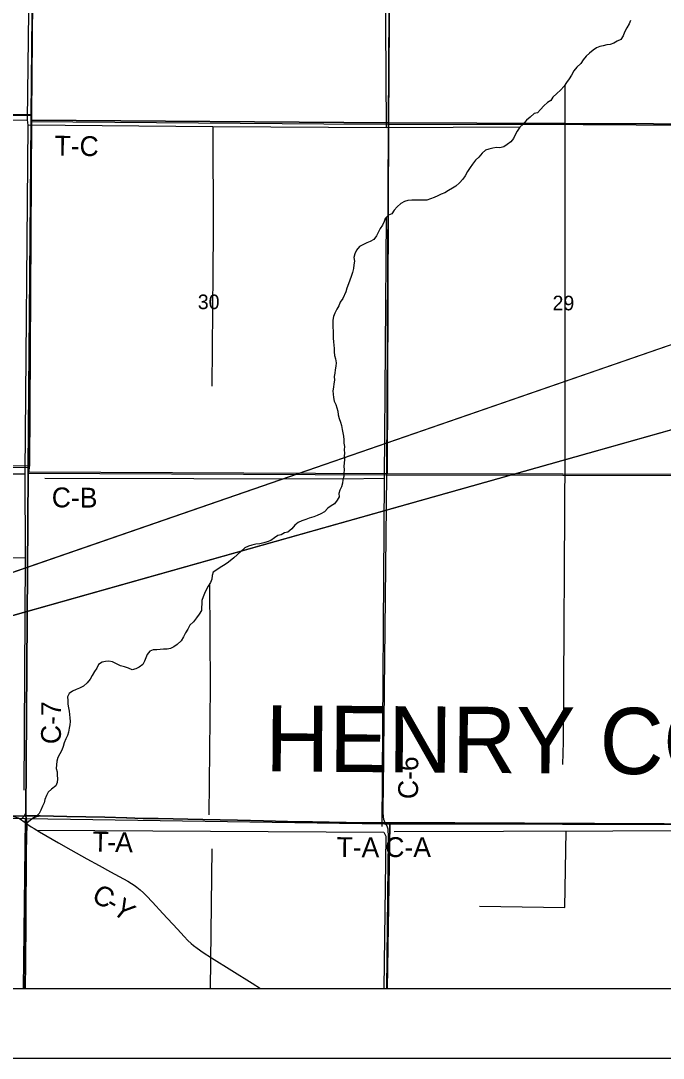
# Model space of a CAD drawing. Extents: x -6.2 to 37.4, y 0.2 to 22.2.
# Drawn here: x 7.181 to 8.101, y 14.207 to 15.692 of the extents above; entities that cross this region are included whole.
import ezdxf

# ---------------------------------------------------------------- set-up
doc = ezdxf.new("R2010")
doc.units = 0
for name, color, linetype in [('GM_X_County_Road', 7, 'Continuous'), ('GM_X_County_Road_Text', 7, 'Continuous'), ('GM_X_County_Text', 7, 'Continuous'), ('GM_X_Minor_River', 7, 'Continuous'), ('GM_X_Rail_Line', 7, 'Continuous'), ('GM_X_Section', 7, 'Continuous'), ('GM_X_Section_Text', 7, 'Continuous'), ('GM_X_Township_Road', 7, 'Continuous'), ('GM_X_Township_Road_Text', 7, 'Continuous'), ('GM_X_US_Shield', 7, 'Continuous'), ('SH_Border', 7, 'Continuous'), ('SH_Cut_Line', 7, 'Continuous'), ('SH_Data', 7, 'Continuous')]:
    doc.layers.add(name, color=color, linetype=linetype)

msp = doc.modelspace()

# ---------------------------------------------------------------- linework, layer by layer
at = {"layer": 'GM_X_County_Road'}
for p, q in [((7.192, 15.0527), (7.1964, 15.5479)), ((7.1964, 15.5479), (7.1965, 15.5566)), ((7.1919, 15.0446), (7.192, 15.0527)), ((7.1813, 14.5491), (7.1862, 14.5537)), ((7.7027, 14.5444), (8.2024, 14.542))]:
    msp.add_line(p, q, dxfattribs=at)
for points in [[(7.1965, 15.5566), (7.1985, 15.7975), (7.2, 16.0484), (7.2001, 16.0575), (7.2066, 16.5579)], [(7.7027, 14.5444), (7.7008, 14.549), (7.7002, 14.5579), (7.7051, 15.0422), (7.7078, 15.5442), (7.7091, 15.7932), (7.71, 16.0457)], [(7.1862, 14.5537), (7.1887, 14.5581), (7.1919, 15.0446)], [(7.1919, 15.0446), (7.7051, 15.0422), (8.2093, 15.0413), (8.4809, 15.0403)], [(7.1813, 14.5491), (7.1841, 14.5472), (7.1878, 14.5446), (7.1899, 14.543)], [(7.1879, 14.3074), (7.1882, 14.344), (7.1886, 14.4031), (7.1892, 14.5025), (7.1899, 14.543)], [(7.1899, 14.543), (7.193, 14.5409), (7.1964, 14.5386), (7.2007, 14.536), (7.208, 14.5316), (7.2353, 14.5157), (7.2528, 14.5057), (7.2759, 14.4929), (7.2935, 14.483), (7.3099, 14.474), (7.3344, 14.4606), (7.3398, 14.4574), (7.3437, 14.4549), (7.3475, 14.4522), (7.3523, 14.4483), (7.357, 14.4442), (7.3613, 14.4398), (7.3698, 14.4307), (7.3846, 14.4147), (7.4057, 14.3919), (7.4151, 14.3816), (7.4206, 14.376), (7.4251, 14.3718), (7.4287, 14.3688), (7.4337, 14.365), (7.4426, 14.3588), (7.4543, 14.3512), (7.5124, 14.315), (7.5245, 14.3074)]]:
    msp.add_lwpolyline(points, dxfattribs=at)
at = {"layer": 'GM_X_Minor_River'}
for p, q in [((7.1283, 15.5492), (7.191, 15.5501)), ((7.1207, 15.0435), (7.1876, 15.0437)), ((7.1186, 14.9231), (7.1883, 14.9241)), ((7.4527, 14.3074), (7.4553, 14.5071))]:
    msp.add_line(p, q, dxfattribs=at)
for points in [[(7.1861, 14.5911), (7.1883, 14.9241), (7.1876, 15.0458), (7.1919, 15.5424), (7.191, 15.5501), (7.1973, 16.0525), (7.2028, 16.4251)], [(7.7046, 15.5387), (7.7036, 15.7599)], [(8.0539, 15.6925), (8.0523, 15.6875), (8.0489, 15.682), (8.0454, 15.6754), (8.0437, 15.6705), (8.0401, 15.665), (8.0348, 15.6629), (8.03, 15.6599), (8.0249, 15.6582), (8.0201, 15.6575), (8.0152, 15.656), (8.0103, 15.655), (8.0055, 15.6534), (8.0006, 15.6498), (7.9956, 15.6458), (7.9907, 15.6411), (7.9865, 15.6362), (7.9829, 15.631), (7.9775, 15.6254), (7.9732, 15.6201), (7.9695, 15.6142), (7.9663, 15.6089), (7.9627, 15.6034), (7.959, 15.5983), (7.9537, 15.5928), (7.9486, 15.5879), (7.943, 15.5828), (7.9402, 15.5779), (7.9352, 15.575), (7.9299, 15.5701), (7.9251, 15.565), (7.9209, 15.5601), (7.916, 15.5592), (7.9107, 15.5541), (7.9052, 15.5495), (7.9006, 15.5442), (7.8958, 15.5395), (7.8918, 15.5342), (7.889, 15.5289), (7.8867, 15.5236), (7.883, 15.5185), (7.8777, 15.5151), (7.8726, 15.5115), (7.8671, 15.5102), (7.8621, 15.5106), (7.857, 15.5095), (7.8515, 15.5082), (7.8466, 15.5067), (7.8416, 15.5025), (7.8369, 15.497), (7.8321, 15.4923), (7.8279, 15.4868), (7.8247, 15.4819), (7.821, 15.4762), (7.8176, 15.4703), (7.814, 15.4654), (7.8092, 15.4599), (7.8039, 15.4554), (7.7991, 15.4522), (7.7934, 15.4491), (7.7881, 15.4459), (7.7831, 15.4437), (7.7784, 15.4414), (7.7733, 15.4392), (7.7626, 15.4354), (7.7573, 15.4352), (7.7522, 15.4354), (7.7465, 15.4353), (7.741, 15.4351), (7.7355, 15.4346), (7.7308, 15.4332), (7.7254, 15.4306), (7.7201, 15.4257), (7.7159, 15.4208), (7.7127, 15.4155), (7.7075, 15.4136), (7.7028, 15.4092), (7.7016, 15.4045), (7.6991, 15.3996), (7.6959, 15.3947), (7.6936, 15.3897), (7.6905, 15.3842), (7.6865, 15.3789), (7.6814, 15.3759), (7.6766, 15.374), (7.6717, 15.3718), (7.6662, 15.3688)], [(7.9602, 15.5999), (7.96, 15.0713), (7.9576, 14.6603), (7.9569, 14.6278)], [(7.8958, 15.5395), (7.7046, 15.5387), (7.4561, 15.5401), (7.1919, 15.5424)], [(7.4561, 15.5401), (7.4569, 15.3909), (7.4561, 15.3323), (7.4548, 15.1691)], [(7.6988, 14.5392), (7.702, 15.0368), (7.7047, 15.411)], [(7.6662, 15.3688), (7.662, 15.3635), (7.6597, 15.3583), (7.6583, 15.353), (7.6589, 15.3479), (7.6581, 15.3428), (7.6575, 15.3375), (7.656, 15.3318), (7.6541, 15.3259), (7.6525, 15.3208), (7.6506, 15.3155), (7.6479, 15.3091), (7.6464, 15.3043), (7.6422, 15.2945), (7.6387, 15.2893), (7.6366, 15.2842), (7.6336, 15.2793), (7.6307, 15.2736), (7.6292, 15.2687), (7.6278, 15.2634), (7.628, 15.2585), (7.628, 15.2533), (7.6285, 15.248), (7.6287, 15.2423), (7.6283, 15.2376), (7.6292, 15.2325), (7.6296, 15.2277), (7.6298, 15.2228), (7.6301, 15.218), (7.6305, 15.2129), (7.6316, 15.208), (7.6327, 15.2025), (7.6321, 15.1975), (7.6313, 15.1926), (7.6309, 15.1875), (7.63, 15.1827), (7.6303, 15.1778), (7.6294, 15.1725), (7.6292, 15.1676), (7.6282, 15.1626), (7.6285, 15.1575), (7.6291, 15.1528), (7.63, 15.1478), (7.6325, 15.1431), (7.6336, 15.1379), (7.6353, 15.1332), (7.6356, 15.1283), (7.6369, 15.1228), (7.6392, 15.1176), (7.6405, 15.1127), (7.6416, 15.1072), (7.6422, 15.1024), (7.6433, 15.0977), (7.6436, 15.0924), (7.644, 15.0876), (7.6446, 15.0829), (7.6443, 15.0781), (7.6449, 15.0734), (7.6441, 15.0687), (7.6445, 15.0639), (7.6437, 15.0544), (7.6442, 15.0495), (7.6436, 15.0447), (7.6436, 15.0398), (7.6425, 15.0351), (7.6417, 15.0301), (7.6403, 15.0252), (7.638, 15.0203), (7.6367, 15.0155), (7.6371, 15.0108), (7.634, 15.0059), (7.6304, 15.0008), (7.6256, 14.9977), (7.6209, 14.9943), (7.6159, 14.9894), (7.611, 14.9864), (7.6057, 14.9838), (7.6007, 14.9819), (7.5941, 14.9802), (7.5893, 14.9783), (7.5838, 14.9765), (7.5785, 14.9738), (7.5737, 14.9704), (7.5693, 14.9649), (7.5636, 14.9604), (7.5589, 14.9593), (7.5539, 14.9566), (7.5492, 14.9553), (7.5443, 14.9519), (7.5391, 14.9483), (7.534, 14.9465), (7.5292, 14.9451), (7.5235, 14.9433), (7.5177, 14.9431), (7.5122, 14.9418), (7.5074, 14.9403), (7.5019, 14.938), (7.4966, 14.9329), (7.491, 14.9276), (7.4861, 14.9233), (7.4813, 14.9191)], [(7.702, 15.0368), (7.6421, 15.0362), (7.216, 15.0368)], [(7.4813, 14.9191), (7.4766, 14.9157), (7.4714, 14.9125), (7.4667, 14.9095), (7.4618, 14.9061), (7.4568, 14.9029), (7.4555, 14.8982), (7.4549, 14.893), (7.4531, 14.8883), (7.4495, 14.883), (7.4467, 14.8777), (7.4444, 14.8726), (7.4423, 14.8675), (7.4407, 14.8623), (7.4405, 14.8574), (7.4401, 14.8527), (7.4401, 14.8479), (7.4368, 14.8428), (7.433, 14.8377), (7.4285, 14.832), (7.4235, 14.8269), (7.4203, 14.8212), (7.4172, 14.8161), (7.4145, 14.8102), (7.4107, 14.8049), (7.4054, 14.7995), (7.4004, 14.7959), (7.3957, 14.7936), (7.3909, 14.7927), (7.3858, 14.7927), (7.3809, 14.7923), (7.3761, 14.792), (7.371, 14.792), (7.3663, 14.7901), (7.3621, 14.7852), (7.3605, 14.7805), (7.3586, 14.7755), (7.3561, 14.7706), (7.351, 14.7668), (7.3459, 14.7644), (7.3406, 14.7633), (7.3354, 14.7655), (7.3298, 14.7675), (7.3241, 14.7688), (7.3127, 14.7745), (7.3074, 14.7755), (7.3025, 14.7752), (7.2977, 14.774), (7.2926, 14.7706), (7.2901, 14.7657), (7.2871, 14.7608), (7.2836, 14.7551), (7.2808, 14.75), (7.2762, 14.7445), (7.271, 14.74), (7.2655, 14.7368), (7.2608, 14.7349), (7.2556, 14.7328), (7.2505, 14.7294), (7.2484, 14.7245), (7.2488, 14.7194), (7.2487, 14.714), (7.2495, 14.7089), (7.2506, 14.704), (7.2513, 14.6992), (7.2517, 14.6945), (7.2519, 14.6894), (7.2517, 14.6846), (7.2507, 14.6795), (7.2495, 14.6742), (7.2484, 14.6694), (7.2459, 14.6643), (7.2434, 14.6588), (7.2419, 14.6533), (7.24, 14.6484), (7.2373, 14.6431), (7.2346, 14.6376), (7.2331, 14.6325), (7.2327, 14.6272), (7.2321, 14.6221), (7.2332, 14.6173), (7.2334, 14.6124), (7.2337, 14.6072), (7.2332, 14.6019), (7.2316, 14.5972), (7.2255, 14.5923), (7.2204, 14.5881), (7.2183, 14.5832), (7.216, 14.5779), (7.215, 14.5731), (7.2125, 14.568), (7.21, 14.5623), (7.2076, 14.5574), (7.2028, 14.5525), (7.1979, 14.5504), (7.1968, 14.5492)], [(7.4514, 14.8858), (7.4524, 14.7391), (7.4504, 14.5558)], [(7.2049, 14.5337), (7.7011, 14.5307), (7.7041, 14.525), (7.7009, 14.3074)], [(7.7156, 14.5319), (8.3418, 14.5336)], [(7.8381, 14.425), (7.9601, 14.4233), (7.9619, 14.5323)]]:
    msp.add_lwpolyline(points, dxfattribs=at)
at = {"layer": 'GM_X_Rail_Line'}
for points in [[(7.1627, 14.5545), (7.1861, 14.554), (7.1887, 14.5541), (7.1885, 14.5584), (7.1918, 15.0448), (7.1919, 15.053), (7.1963, 15.5481), (7.1964, 15.5569), (7.1984, 15.7978)], [(7.1984, 15.7978), (7.1964, 15.5569), (7.1963, 15.5481), (7.1919, 15.053), (7.1918, 15.0448), (7.1885, 14.5584), (7.1887, 14.5541), (7.2023, 14.5544), (7.2092, 14.5544), (7.2473, 14.5533), (7.3018, 14.5523), (7.3329, 14.5515), (7.3563, 14.5507), (7.378, 14.5504), (7.4418, 14.5491), (7.4916, 14.5481), (7.529, 14.547), (7.5632, 14.5462), (7.599, 14.5455), (7.6472, 14.5447), (7.6721, 14.5445), (7.6943, 14.5445), (7.7025, 14.5447), (8.2023, 14.5423)], [(5.0809, 14.3074), (7.1878, 14.3074), (7.1881, 14.3443), (7.1885, 14.4033), (7.189, 14.5028), (7.1898, 14.5432), (7.1887, 14.5541), (7.1861, 14.554), (7.1627, 14.5545)], [(8.2023, 14.5423), (7.7025, 14.5447), (7.6943, 14.5445), (7.6721, 14.5445), (7.6472, 14.5447), (7.599, 14.5455), (7.5632, 14.5462), (7.529, 14.547), (7.4916, 14.5481), (7.4418, 14.5491), (7.378, 14.5504), (7.3563, 14.5507), (7.3329, 14.5515), (7.3018, 14.5523), (7.2473, 14.5533), (7.2092, 14.5544), (7.2023, 14.5544), (7.1887, 14.5541), (7.1898, 14.5432), (7.189, 14.5028), (7.1885, 14.4033), (7.1881, 14.3443), (7.1878, 14.3074), (8.4809, 14.3074)]]:
    msp.add_lwpolyline(points, dxfattribs=at)
at = {"layer": 'GM_X_Section'}
for points in [[(7.201, 16.0586), (7.2008, 16.0497), (7.1968, 15.5575), (6.6989, 15.5603), (6.7037, 16.063)], [(7.2008, 16.0497), (7.7109, 16.0475), (7.7079, 15.546), (7.1969, 15.5497), (7.1967, 15.5531), (7.1968, 15.5575)], [(7.7109, 16.0475), (8.2131, 16.0441), (8.2135, 15.5438), (7.7079, 15.546)], [(6.6989, 15.5603), (7.1968, 15.5575), (7.1967, 15.5531), (7.1969, 15.5497), (7.1936, 15.0544), (6.6946, 15.0595), (6.6989, 15.5584)], [(7.1969, 15.5497), (7.7079, 15.546), (7.7058, 15.0438), (7.1934, 15.0459), (7.1936, 15.0544)], [(7.7079, 15.546), (8.2135, 15.5438), (8.2085, 15.0429), (7.7058, 15.0438)]]:
    msp.add_lwpolyline(points, close=True, dxfattribs=at)
at = {"layer": 'GM_X_Township_Road'}
for p, q in [((6.6987, 15.5585), (7.1965, 15.5566)), ((7.1965, 15.5566), (7.1964, 15.5479)), ((6.6951, 15.0571), (7.192, 15.0527)), ((7.7027, 14.5444), (8.2024, 14.542))]:
    msp.add_line(p, q, dxfattribs=at)
for points in [[(7.1964, 15.5479), (7.615, 15.5444), (7.7078, 15.5442)], [(7.7078, 15.5442), (7.9862, 15.5435), (8.2136, 15.542)], [(7.0273, 14.5562), (7.0346, 14.5551), (7.0393, 14.5547), (7.1622, 14.554), (7.1671, 14.5536), (7.1707, 14.5533), (7.173, 14.553), (7.1745, 14.5525), (7.1759, 14.552), (7.1774, 14.5513), (7.1794, 14.5503), (7.1813, 14.5491)], [(7.1813, 14.5491), (7.1841, 14.5472), (7.1878, 14.5446), (7.1899, 14.543)], [(7.1899, 14.543), (7.1915, 14.5449), (7.1931, 14.5466), (7.1946, 14.5482), (7.197, 14.5502), (7.1983, 14.5511), (7.1996, 14.5519), (7.201, 14.5525), (7.2024, 14.5531), (7.204, 14.5534), (7.2055, 14.5536), (7.2068, 14.5538), (7.2093, 14.5541)], [(7.2923, 14.5522), (7.2475, 14.553), (7.2093, 14.5541)], [(7.6197, 14.5449), (7.5991, 14.5453), (7.5633, 14.546), (7.5291, 14.5467), (7.4917, 14.5478), (7.442, 14.5489), (7.3782, 14.5501), (7.3564, 14.5505), (7.333, 14.5512), (7.3019, 14.552), (7.2923, 14.5522)], [(7.7027, 14.5444), (7.6944, 14.5442), (7.6722, 14.5442), (7.6473, 14.5444), (7.6197, 14.5449)], [(7.7054, 14.3074), (7.706, 14.3518), (7.7073, 14.4823), (7.7077, 14.5181), (7.7077, 14.5274), (7.7074, 14.532), (7.707, 14.5351), (7.7064, 14.5382), (7.7049, 14.5414), (7.7027, 14.5444)]]:
    msp.add_lwpolyline(points, dxfattribs=at)
at = {"layer": 'GM_X_US_Shield'}
for points in [[(6.6867, 14.3074), (7.1853, 14.3074), (7.1882, 14.55), (6.6887, 14.557)], [(7.1853, 14.3074), (7.7056, 14.3074), (7.7094, 14.5424), (7.702, 14.5424), (7.1882, 14.55)], [(7.7056, 14.3074), (8.2089, 14.3074), (8.2136, 14.5414), (8.2034, 14.5414), (7.7094, 14.5424)]]:
    msp.add_lwpolyline(points, close=True, dxfattribs=at)
at = {"layer": 'SH_Border'}
for p, q in [((6.1881, 14.564), (8.9944, 15.5335)), ((8.9944, 15.3553), (6.1881, 14.564))]:
    msp.add_line(p, q, dxfattribs=at)
at = {"layer": 'SH_Cut_Line'}
for points in [[(8.2023, 14.5423), (7.7025, 14.5447), (7.6943, 14.5445), (7.6721, 14.5445), (7.6472, 14.5447), (7.599, 14.5455), (7.5632, 14.5462), (7.529, 14.547), (7.4916, 14.5481), (7.4418, 14.5491), (7.378, 14.5504), (7.3563, 14.5507), (7.3329, 14.5515), (7.3018, 14.5523), (7.2473, 14.5533), (7.2092, 14.5544), (7.2023, 14.5544), (7.1887, 14.5541), (7.1861, 14.554), (7.1627, 14.5545)], [(7.1627, 14.5545), (7.1861, 14.554), (7.1887, 14.5541), (7.2023, 14.5544), (7.2092, 14.5544), (7.2473, 14.5533), (7.3018, 14.5523), (7.3329, 14.5515), (7.3563, 14.5507), (7.378, 14.5504), (7.4418, 14.5491), (7.4916, 14.5481), (7.529, 14.547), (7.5632, 14.5462), (7.599, 14.5455), (7.6472, 14.5447), (7.6721, 14.5445), (7.6943, 14.5445), (7.7025, 14.5447), (8.2023, 14.5423)], [(5.0809, 14.3074), (8.4809, 14.3074)]]:
    msp.add_lwpolyline(points, dxfattribs=at)
at = {"layer": 'SH_Data'}
for p, q in [((1.6809, 14.3074), (8.4809, 14.3074)), ((1.5809, 14.2074), (8.5809, 14.2074))]:
    msp.add_line(p, q, dxfattribs=at)
msp.add_lwpolyline([(8.9944, 15.3553), (6.1881, 14.564), (8.9944, 15.5335)], close=True, dxfattribs=at)

# ---------------------------------------------------------------- texts
at = {"layer": 'GM_X_County_Road_Text'}
for s, height, rotation, p in [('C-B', 0.02841, 359.588, (7.2256, 14.9958)), ('C-7', 0.02841, 89.5419, (7.2387, 14.6568)), ('C-6', 0.02841, 89.5419, (7.7499, 14.5781)), ('C-A', 0.02841, 0, (7.7031, 14.4953)), ('C', 0.0284, 330.8612, (7.2811, 14.4335)), ('-', 0.0284, 330.1796, (7.3014, 14.4222)), ('Y', 0.0284, 321.0569, (7.3106, 14.417))]:
    msp.add_text(s, height=height, rotation=rotation, dxfattribs=at).set_placement(p)
at = {"layer": 'GM_X_County_Text'}
msp.add_text('HENRY COUNTY', height=0.094697, rotation=359.5807, dxfattribs=at).set_placement((7.5312, 14.6179))
at = {"layer": 'GM_X_Section_Text'}
for s, p in [('30', (7.4347, 15.2793)), ('29', (7.9425, 15.2776))]:
    msp.add_text(s, height=0.02093, rotation=0, dxfattribs=at).set_placement(p)
at = {"layer": 'GM_X_Township_Road_Text'}
for s, height, rotation, p in [('T-C', 0.02841, 359.1454, (7.2294, 15.4991)), ('T', 0.0284, 358.5973, (7.2836, 14.5035)), ('A', 0.0284, 358.4387, (7.3163, 14.5027)), ('T-A', 0.02841, 359.5755, (7.6333, 14.4954)), ('-', 0.0284, 358.4549, (7.3048, 14.503))]:
    msp.add_text(s, height=height, rotation=rotation, dxfattribs=at).set_placement(p)

doc.saveas('drawing.dxf')
